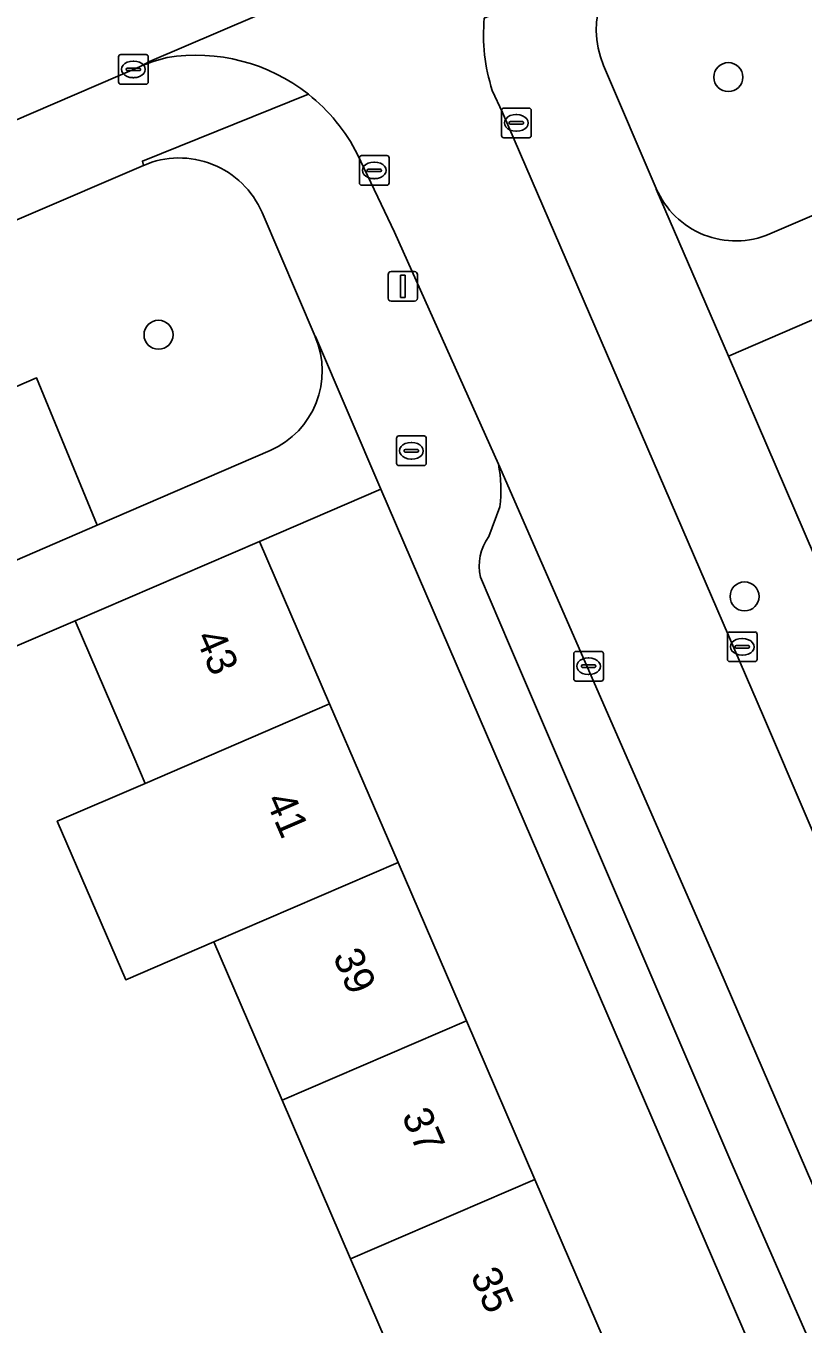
# Model space of a CAD drawing. Extents: x 159352 to 160617, y 385888 to 387323.
# Drawn here: x 159569.99 to 159596.19, y 386350.14 to 386393.94 of the extents above; entities that cross this region are included whole.
import ezdxf

# ---------------------------------------------------------------- set-up
doc = ezdxf.new("R2010")
doc.units = 0
for name, color, linetype in [('IMGEO_Boom', 7, 'Continuous'), ('IMGEO_Brandkraan', 7, 'Continuous'), ('IMGEO_Erf', 7, 'Continuous'), ('IMGEO_Groenvoorziening', 7, 'Continuous'), ('IMGEO_Kolk', 7, 'Continuous'), ('IMGEO_Lichtmast', 7, 'Continuous'), ('IMGEO_Muur', 7, 'Continuous'), ('IMGEO_Pand', 7, 'Continuous'), ('IMGEO_Pand_nummerreeks', 7, 'Continuous'), ('IMGEO_Parkeervlak_open', 7, 'Continuous'), ('IMGEO_Rijbaan_lokaal_gesloten', 7, 'Continuous'), ('IMGEO_Rijbaan_lokaal_open', 7, 'Continuous'), ('IMGEO_Voetpad_open', 7, 'Continuous')]:
    doc.layers.add(name, color=color, linetype=linetype)

msp = doc.modelspace()

# ---------------------------------------------------------------- linework, layer by layer
at = {"layer": 'IMGEO_Boom'}
for centre in [(159593.672, 386392.211), (159574.46, 386383.517), (159594.219, 386374.689)]:
    msp.add_circle(centre, 0.489, dxfattribs=at)
at = {"layer": 'IMGEO_Brandkraan'}
for p, q in [((159582.485, 386379.176), (159582.485, 386380.028)), ((159582.56, 386380.102), (159583.412, 386380.102)), ((159583.486, 386380.028), (159583.486, 386379.176)), ((159582.744, 386379.596), (159582.744, 386379.608)), ((159583.182, 386379.559), (159582.784, 386379.559)), ((159582.787, 386379.645), (159583.185, 386379.645)), ((159582.973, 386379.882), (159582.998, 386379.882)), ((159583.228, 386379.608), (159583.228, 386379.596)), ((159582.996, 386379.322), (159582.971, 386379.322)), ((159583.412, 386379.102), (159582.56, 386379.102))]:
    msp.add_line(p, q, dxfattribs=at)
for points in [[(159582.485, 386379.176), (159582.485, 386380.028)], [(159582.56, 386380.102), (159583.412, 386380.102)], [(159583.486, 386380.028), (159583.486, 386379.176)], [(159583.412, 386379.102), (159582.56, 386379.102)]]:
    msp.add_lwpolyline(points, dxfattribs=at)
for centre, radius, start, end in [((159582.562, 386380.026), 0.0765, 91.552, 178.448), ((159582.562, 386380.026), 0.0765, 91.552, 178.448), ((159583.41, 386380.026), 0.0765, 1.552, 88.448), ((159583.41, 386380.026), 0.0765, 1.552, 88.448), ((159582.784, 386379.605), 0.0403, 85.8775, 175.7526), ((159582.781, 386379.595), 0.0366, 178.938, 274.7102), ((159583.185, 386379.602), 0.043, 264.8664, 352.4533), ((159583.189, 386379.607), 0.0386, 1.7309, 96.639), ((159582.562, 386379.178), 0.0765, 181.552, 268.448), ((159582.562, 386379.178), 0.0765, 181.552, 268.448), ((159583.41, 386379.178), 0.0765, 271.552, 358.448), ((159583.41, 386379.178), 0.0765, 271.552, 358.448)]:
    msp.add_arc(centre, radius, start, end, dxfattribs=at)
for centre, major_axis, ratio, start_param, end_param in [((159582.972, 386379.602), (-0.387, 0.002), 0.722429, 4.712389, 7.853982), ((159582.997, 386379.602), (-0.39, 0.002), 0.717154, 1.570796, 4.712389)]:
    msp.add_ellipse(centre, major_axis=major_axis, ratio=ratio, start_param=start_param, end_param=end_param, dxfattribs=at)
at = {"layer": 'IMGEO_Erf'}
for points in [[(159613.248, 386347.3), (159610.951, 386352.643), (159608.654, 386357.986), (159606.357, 386363.329), (159604.06, 386368.673), (159601.763, 386374.016), (159599.467, 386379.359), (159597.313, 386384.368), (159593.672, 386382.792), (159613.28, 386337.251)], [(159601.784, 386332.309), (159581.955, 386378.311), (159577.866, 386376.545), (159580.23, 386371.06), (159582.535, 386365.713), (159584.84, 386360.365), (159587.145, 386355.018), (159589.45, 386349.67)], [(159583.235, 386346.991), (159580.93, 386352.338), (159578.625, 386357.686), (159576.32, 386363.033), (159573.353, 386361.753), (159571.046, 386367.1), (159574.015, 386368.38), (159573.629, 386369.275), (159571.65, 386373.866), (159557.885, 386367.96)]]:
    msp.add_lwpolyline(points, dxfattribs=at)
at = {"layer": 'IMGEO_Groenvoorziening'}
for points in [[(159595.07, 386386.919), (159601.716, 386389.772), (159599.563, 386394.773), (159600.699, 386395.262), (159598.476, 386399.791), (159591.041, 386396.57)], [(159589.464, 386392.605), (159591.244, 386388.449)], [(159573.956, 386389.234), (159566.026, 386385.827), (159568.052, 386381.076), (159570.344, 386382.066), (159572.392, 386377.09), (159578.225, 386379.616)], [(159579.744, 386383.454), (159577.95, 386387.642)]]:
    msp.add_lwpolyline(points, dxfattribs=at)
msp.add_lwpolyline([(159554.779, 386375.346), (159556.921, 386370.389), (159572.392, 386377.09), (159570.344, 386382.066), (159568.052, 386381.076)], close=True, dxfattribs=at)
for centre, radius, start, end in [((159592.244, 386393.795), 3.024, 113.4437, 203.1779), ((159575.159, 386386.447), 3.036, 23.1864, 113.3494), ((159593.921, 386389.595), 2.912, 203.1747, 293.2328), ((159577.051, 386382.3), 2.93, 293.6282, 23.1866)]:
    msp.add_arc(centre, radius, start, end, dxfattribs=at)
at = {"layer": 'IMGEO_Kolk'}
for p, q in [((159573.113, 386392.047), (159573.113, 386392.899)), ((159573.188, 386392.973), (159574.04, 386392.973)), ((159573.601, 386392.753), (159573.626, 386392.753)), ((159574.114, 386392.899), (159574.114, 386392.047)), ((159573.372, 386392.467), (159573.372, 386392.479)), ((159573.81, 386392.43), (159573.412, 386392.43)), ((159573.415, 386392.516), (159573.813, 386392.516)), ((159573.856, 386392.479), (159573.856, 386392.467)), ((159574.04, 386391.973), (159573.188, 386391.973)), ((159573.624, 386392.193), (159573.599, 386392.193)), ((159586.024, 386390.242), (159586.024, 386391.094)), ((159586.099, 386391.168), (159586.951, 386391.168)), ((159586.512, 386390.948), (159586.537, 386390.948)), ((159587.025, 386391.094), (159587.025, 386390.242)), ((159586.283, 386390.662), (159586.283, 386390.674)), ((159586.721, 386390.625), (159586.323, 386390.625)), ((159586.326, 386390.711), (159586.724, 386390.711)), ((159586.767, 386390.674), (159586.767, 386390.662)), ((159586.951, 386390.168), (159586.099, 386390.168)), ((159586.535, 386390.388), (159586.51, 386390.388)), ((159581.233, 386388.639), (159581.233, 386389.491)), ((159581.308, 386389.565), (159582.16, 386389.565)), ((159581.721, 386389.345), (159581.746, 386389.345)), ((159582.234, 386389.491), (159582.234, 386388.639)), ((159581.492, 386389.059), (159581.492, 386389.071)), ((159581.93, 386389.022), (159581.532, 386389.022)), ((159581.535, 386389.108), (159581.933, 386389.108)), ((159581.744, 386388.785), (159581.719, 386388.785)), ((159581.976, 386389.071), (159581.976, 386389.059)), ((159582.16, 386388.565), (159581.308, 386388.565)), ((159593.715, 386373.488), (159594.567, 386373.488)), ((159593.64, 386372.562), (159593.64, 386373.414)), ((159593.899, 386372.982), (159593.899, 386372.994)), ((159593.942, 386373.031), (159594.34, 386373.031)), ((159594.128, 386373.268), (159594.153, 386373.268)), ((159594.383, 386372.994), (159594.383, 386372.982)), ((159594.641, 386373.414), (159594.641, 386372.562)), ((159588.459, 386371.908), (159588.459, 386372.76)), ((159588.534, 386372.834), (159589.386, 386372.834)), ((159588.947, 386372.614), (159588.972, 386372.614)), ((159589.46, 386372.76), (159589.46, 386371.908)), ((159594.337, 386372.945), (159593.939, 386372.945)), ((159594.151, 386372.708), (159594.126, 386372.708)), ((159588.718, 386372.328), (159588.718, 386372.34)), ((159589.156, 386372.291), (159588.758, 386372.291)), ((159588.761, 386372.377), (159589.159, 386372.377)), ((159589.202, 386372.34), (159589.202, 386372.328)), ((159594.567, 386372.488), (159593.715, 386372.488)), ((159589.386, 386371.834), (159588.534, 386371.834)), ((159588.97, 386372.054), (159588.945, 386372.054))]:
    msp.add_line(p, q, dxfattribs=at)
for points in [[(159573.113, 386392.047), (159573.113, 386392.899)], [(159573.188, 386392.973), (159574.04, 386392.973)], [(159574.114, 386392.899), (159574.114, 386392.047)], [(159574.04, 386391.973), (159573.188, 386391.973)], [(159586.024, 386390.242), (159586.024, 386391.094)], [(159586.099, 386391.168), (159586.951, 386391.168)], [(159587.025, 386391.094), (159587.025, 386390.242)], [(159586.951, 386390.168), (159586.099, 386390.168)], [(159581.233, 386388.639), (159581.233, 386389.491)], [(159581.308, 386389.565), (159582.16, 386389.565)], [(159582.234, 386389.491), (159582.234, 386388.639)], [(159582.16, 386388.565), (159581.308, 386388.565)], [(159593.715, 386373.488), (159594.567, 386373.488)], [(159593.64, 386372.562), (159593.64, 386373.414)], [(159594.641, 386373.414), (159594.641, 386372.562)], [(159588.459, 386371.908), (159588.459, 386372.76)], [(159588.534, 386372.834), (159589.386, 386372.834)], [(159589.46, 386372.76), (159589.46, 386371.908)], [(159594.567, 386372.488), (159593.715, 386372.488)], [(159589.386, 386371.834), (159588.534, 386371.834)]]:
    msp.add_lwpolyline(points, dxfattribs=at)
for centre, radius, start, end in [((159573.19, 386392.897), 0.0765, 91.552, 178.448), ((159573.19, 386392.897), 0.0765, 91.552, 178.448), ((159574.038, 386392.897), 0.0765, 1.552, 88.448), ((159574.038, 386392.897), 0.0765, 1.552, 88.448), ((159573.412, 386392.476), 0.0403, 85.8775, 175.7526), ((159573.409, 386392.466), 0.0366, 178.938, 274.7102), ((159573.813, 386392.473), 0.043, 264.8664, 352.4533), ((159573.817, 386392.478), 0.0386, 1.7309, 96.639), ((159573.19, 386392.049), 0.0765, 181.552, 268.448), ((159573.19, 386392.049), 0.0765, 181.552, 268.448), ((159574.038, 386392.049), 0.0765, 271.552, 358.448), ((159574.038, 386392.049), 0.0765, 271.552, 358.448), ((159586.101, 386391.092), 0.0765, 91.552, 178.448), ((159586.101, 386391.092), 0.0765, 91.552, 178.448), ((159586.949, 386391.092), 0.0765, 1.552, 88.448), ((159586.949, 386391.092), 0.0765, 1.552, 88.448), ((159586.323, 386390.671), 0.0403, 85.8775, 175.7526), ((159586.32, 386390.661), 0.0366, 178.938, 274.7102), ((159586.724, 386390.668), 0.043, 264.8664, 352.4533), ((159586.728, 386390.673), 0.0386, 1.7309, 96.639), ((159586.101, 386390.244), 0.0765, 181.552, 268.448), ((159586.101, 386390.244), 0.0765, 181.552, 268.448), ((159586.949, 386390.244), 0.0765, 271.552, 358.448), ((159586.949, 386390.244), 0.0765, 271.552, 358.448), ((159581.31, 386389.489), 0.0765, 91.552, 178.448), ((159581.31, 386389.489), 0.0765, 91.552, 178.448), ((159582.158, 386389.489), 0.0765, 1.552, 88.448), ((159582.158, 386389.489), 0.0765, 1.552, 88.448), ((159581.532, 386389.068), 0.0403, 85.8775, 175.7526), ((159581.529, 386389.058), 0.0366, 178.938, 274.7102), ((159581.933, 386389.065), 0.043, 264.8664, 352.4533), ((159581.937, 386389.07), 0.0386, 1.7309, 96.639), ((159581.31, 386388.641), 0.0765, 181.552, 268.448), ((159581.31, 386388.641), 0.0765, 181.552, 268.448), ((159582.158, 386388.641), 0.0765, 271.552, 358.448), ((159582.158, 386388.641), 0.0765, 271.552, 358.448), ((159593.717, 386373.412), 0.0765, 91.552, 178.448), ((159593.717, 386373.412), 0.0765, 91.552, 178.448), ((159594.565, 386373.412), 0.0765, 1.552, 88.448), ((159594.565, 386373.412), 0.0765, 1.552, 88.448), ((159593.939, 386372.991), 0.0403, 85.8775, 175.7526), ((159594.344, 386372.993), 0.0386, 1.7309, 96.639), ((159588.536, 386372.758), 0.0765, 91.552, 178.448), ((159588.536, 386372.758), 0.0765, 91.552, 178.448), ((159589.384, 386372.758), 0.0765, 1.552, 88.448), ((159589.384, 386372.758), 0.0765, 1.552, 88.448), ((159593.717, 386372.564), 0.0765, 181.552, 268.448), ((159593.717, 386372.564), 0.0765, 181.552, 268.448), ((159593.936, 386372.981), 0.0366, 178.938, 274.7102), ((159594.34, 386372.988), 0.043, 264.8664, 352.4533), ((159594.565, 386372.564), 0.0765, 271.552, 358.448), ((159594.565, 386372.564), 0.0765, 271.552, 358.448), ((159588.758, 386372.337), 0.0403, 85.8775, 175.7526), ((159588.755, 386372.327), 0.0366, 178.938, 274.7102), ((159589.159, 386372.334), 0.043, 264.8664, 352.4533), ((159589.163, 386372.339), 0.0386, 1.7309, 96.639), ((159588.536, 386371.91), 0.0765, 181.552, 268.448), ((159588.536, 386371.91), 0.0765, 181.552, 268.448), ((159589.384, 386371.91), 0.0765, 271.552, 358.448), ((159589.384, 386371.91), 0.0765, 271.552, 358.448)]:
    msp.add_arc(centre, radius, start, end, dxfattribs=at)
for centre, major_axis, ratio, start_param, end_param in [((159573.6, 386392.473), (-0.387, 0.002), 0.722429, 4.712389, 7.853982), ((159573.625, 386392.473), (-0.39, 0.002), 0.717154, 1.570796, 4.712389), ((159586.511, 386390.668), (-0.387, 0.002), 0.722429, 4.712389, 7.853982), ((159586.536, 386390.668), (-0.39, 0.002), 0.717154, 1.570796, 4.712389), ((159581.72, 386389.065), (-0.387, 0.002), 0.722429, 4.712389, 7.853982), ((159581.745, 386389.065), (-0.39, 0.002), 0.717154, 1.570796, 4.712389), ((159594.127, 386372.988), (-0.387, 0.002), 0.722429, 4.712389, 7.853982), ((159594.152, 386372.988), (-0.39, 0.002), 0.717154, 1.570796, 4.712389), ((159588.946, 386372.334), (-0.387, 0.002), 0.722429, 4.712389, 7.853982), ((159588.971, 386372.334), (-0.39, 0.002), 0.717154, 1.570796, 4.712389)]:
    msp.add_ellipse(centre, major_axis=major_axis, ratio=ratio, start_param=start_param, end_param=end_param, dxfattribs=at)
at = {"layer": 'IMGEO_Lichtmast'}
for p, q in [((159582.201, 386384.751), (159582.201, 386385.551)), ((159582.201, 386385.551), (159582.201, 386384.751)), ((159582.301, 386385.651), (159583.091, 386385.651)), ((159583.091, 386385.651), (159582.301, 386385.651)), ((159583.191, 386385.551), (159583.191, 386384.751)), ((159583.191, 386384.751), (159583.191, 386385.551)), ((159583.091, 386384.651), (159582.301, 386384.651)), ((159582.301, 386384.651), (159583.091, 386384.651))]:
    msp.add_line(p, q, dxfattribs=at)
msp.add_lwpolyline([(159582.621, 386385.526), (159582.771, 386385.526), (159582.771, 386384.776), (159582.621, 386384.776), (159582.621, 386385.526)], dxfattribs=at)
for centre, start, end in [((159582.301, 386385.551), 90, 180), ((159582.301, 386385.551), 90, 180), ((159583.091, 386385.551), 0, 90), ((159583.091, 386385.551), 360, 90), ((159582.301, 386384.751), 180, 270), ((159582.301, 386384.751), 180, 270), ((159583.091, 386384.751), 270, 0), ((159583.091, 386384.751), 270, 0)]:
    msp.add_arc(centre, 0.1, start, end, dxfattribs=at)
at = {"layer": 'IMGEO_Muur'}
msp.add_lwpolyline([(159571.65, 386373.866), (159557.885, 386367.96)], dxfattribs=at)
at = {"layer": 'IMGEO_Pand'}
for points in [[(159571.65, 386373.866), (159573.629, 386369.275), (159574.015, 386368.38), (159580.23, 386371.06), (159577.866, 386376.545)], [(159580.23, 386371.06), (159574.015, 386368.38), (159571.046, 386367.1), (159573.353, 386361.753), (159576.32, 386363.033), (159582.535, 386365.713)], [(159576.32, 386363.033), (159578.625, 386357.686), (159584.84, 386360.365), (159582.535, 386365.713)], [(159587.145, 386355.018), (159584.84, 386360.365), (159578.625, 386357.686), (159580.93, 386352.338)], [(159589.45, 386349.67), (159587.145, 386355.018), (159580.93, 386352.338), (159583.235, 386346.991)]]:
    msp.add_lwpolyline(points, close=True, dxfattribs=at)
at = {"layer": 'IMGEO_Parkeervlak_open'}
for points in [[(159613.771, 386314.865), (159607.659, 386329.022), (159607.2, 386328.824), (159605.714, 386332.267), (159606.173, 386332.465), (159602.481, 386341.017), (159593.385, 386362.094), (159585.918, 386379.157)], [(159585.969, 386377.712), (159585.598, 386376.71)], [(159585.318, 386375.34), (159586.299, 386373.039), (159593.761, 386355.621), (159597.74, 386346.498), (159619.334, 386296.216), (159623.749, 386286.105), (159625.224, 386282.726), (159625.986, 386280.957), (159627.387, 386277.707), (159633.968, 386262.437), (159639.667, 386249.309)]]:
    msp.add_lwpolyline(points, dxfattribs=at)
for centre, radius, start, end in [((159581.563, 386378.28), 4.442, 352.6547, 11.388), ((159586.926, 386375.725), 1.653, 143.4316, 193.4664)]:
    msp.add_arc(centre, radius, start, end, dxfattribs=at)
at = {"layer": 'IMGEO_Rijbaan_lokaal_gesloten'}
msp.add_lwpolyline([(159528.635, 386373.023), (159553.089, 386383.626), (159573.819, 386392.563), (159574.155, 386392.734), (159588.442, 386398.856), (159589.316, 386399.232), (159596.446, 386402.306), (159634.239, 386418.643)], dxfattribs=at)
at = {"layer": 'IMGEO_Rijbaan_lokaal_open'}
for points in [[(159588.442, 386398.856), (159574.155, 386392.734), (159573.819, 386392.563)], [(159612.087, 386330.702), (159610.591, 386334.174), (159600.709, 386356.954), (159594.852, 386370.635), (159586.058, 386391.017), (159585.714, 386391.763)], [(159581.169, 386389.603), (159582.416, 386386.983), (159585.918, 386379.157), (159593.385, 386362.094), (159602.481, 386341.017), (159606.173, 386332.465), (159607.659, 386329.022), (159613.771, 386314.865), (159632.443, 386271.492), (159641.663, 386250), (159643.001, 386246.882), (159644.38, 386243.667)]]:
    msp.add_lwpolyline(points, dxfattribs=at)
for centre, radius, start, end in [((159591.457, 386393.633), 6.04, 174.6113, 198.033), ((159576.095, 386387.229), 5.799, 103.4246, 113.1123), ((159575.732, 386386.857), 6.093, 51.6187, 99.2816), ((159575.722, 386386.854), 6.101, 26.7814, 51.5634)]:
    msp.add_arc(centre, radius, start, end, dxfattribs=at)
at = {"layer": 'IMGEO_Voetpad_open'}
for points in [[(159585.444, 386394.2), (159591.041, 386396.57), (159598.476, 386399.791), (159611.57, 386405.463), (159613.575, 386400.803), (159615.733, 386395.788), (159601.716, 386389.772), (159595.07, 386386.919)], [(159591.244, 386388.449), (159591.241, 386388.436), (159593.672, 386382.792), (159597.313, 386384.368), (159597.111, 386384.839), (159603.253, 386387.479), (159617.002, 386393.419), (159618.339, 386393.996), (159632.112, 386399.947)], [(159573.819, 386392.563), (159553.089, 386383.626), (159528.635, 386373.023)], [(159635.593, 386285.426), (159634.976, 386286.859), (159613.806, 386336.028), (159613.28, 386337.251), (159593.672, 386382.792), (159591.241, 386388.436), (159591.244, 386388.449), (159589.464, 386392.605)], [(159573.956, 386389.234), (159573.916, 386389.376), (159579.515, 386391.633)], [(159579.515, 386391.633), (159573.916, 386389.376), (159573.956, 386389.234)], [(159585.714, 386391.763), (159586.058, 386391.017), (159594.852, 386370.635), (159600.709, 386356.954), (159610.591, 386334.174), (159610.805, 386334.266), (159611.264, 386334.463), (159612.758, 386330.99), (159612.299, 386330.793), (159612.087, 386330.702), (159620.992, 386310.031)], [(159578.225, 386379.616), (159572.392, 386377.09), (159556.921, 386370.389), (159554.779, 386375.346), (159552.719, 386380.111), (159566.026, 386385.827), (159573.956, 386389.234)], [(159582.416, 386386.983), (159581.169, 386389.603)], [(159577.95, 386387.642), (159579.744, 386383.454), (159579.748, 386383.454), (159581.955, 386378.311), (159601.784, 386332.309), (159602.346, 386331.006), (159622.279, 386284.764), (159623.749, 386286.105), (159619.334, 386296.216), (159597.74, 386346.498), (159593.761, 386355.621), (159586.299, 386373.039), (159585.318, 386375.34)], [(159585.918, 386379.157), (159582.416, 386386.983)], [(159530.608, 386362.272), (159530.576, 386362.156), (159532.833, 386357.179), (159536.57, 386358.8), (159542.759, 386361.47), (159556.517, 386367.373), (159557.885, 386367.96), (159571.65, 386373.866), (159577.866, 386376.545), (159581.955, 386378.311), (159579.748, 386383.454), (159579.744, 386383.454)], [(159585.598, 386376.71), (159585.969, 386377.712)]]:
    msp.add_lwpolyline(points, dxfattribs=at)
for centre, radius, start, end in [((159592.244, 386393.795), 3.024, 113.4437, 203.1779), ((159591.457, 386393.633), 6.04, 174.6113, 198.033), ((159576.095, 386387.229), 5.799, 103.4246, 113.1123), ((159575.732, 386386.857), 6.093, 51.6187, 99.2816), ((159575.722, 386386.854), 6.101, 26.7814, 51.5634), ((159575.159, 386386.447), 3.036, 23.1864, 113.3494), ((159593.921, 386389.595), 2.912, 203.1747, 293.2328), ((159577.051, 386382.3), 2.93, 293.6282, 23.1866), ((159581.563, 386378.28), 4.442, 352.6547, 11.388), ((159586.926, 386375.725), 1.653, 143.4316, 193.4664)]:
    msp.add_arc(centre, radius, start, end, dxfattribs=at)

# ---------------------------------------------------------------- texts
at = {"layer": 'IMGEO_Pand_nummerreeks'}
for s, rotation, p in [('43', 293.317, (159575.687, 386373.315)), ('41', 293.3192, (159578.05, 386367.828)), ('39', 293.317, (159580.326, 386362.551)), ('37', 293.317, (159582.646, 386357.169)), ('35', 293.317, (159584.966, 386351.787))]:
    msp.add_text(s, height=1, rotation=rotation, dxfattribs=at).set_placement(p)

doc.saveas('drawing.dxf')
